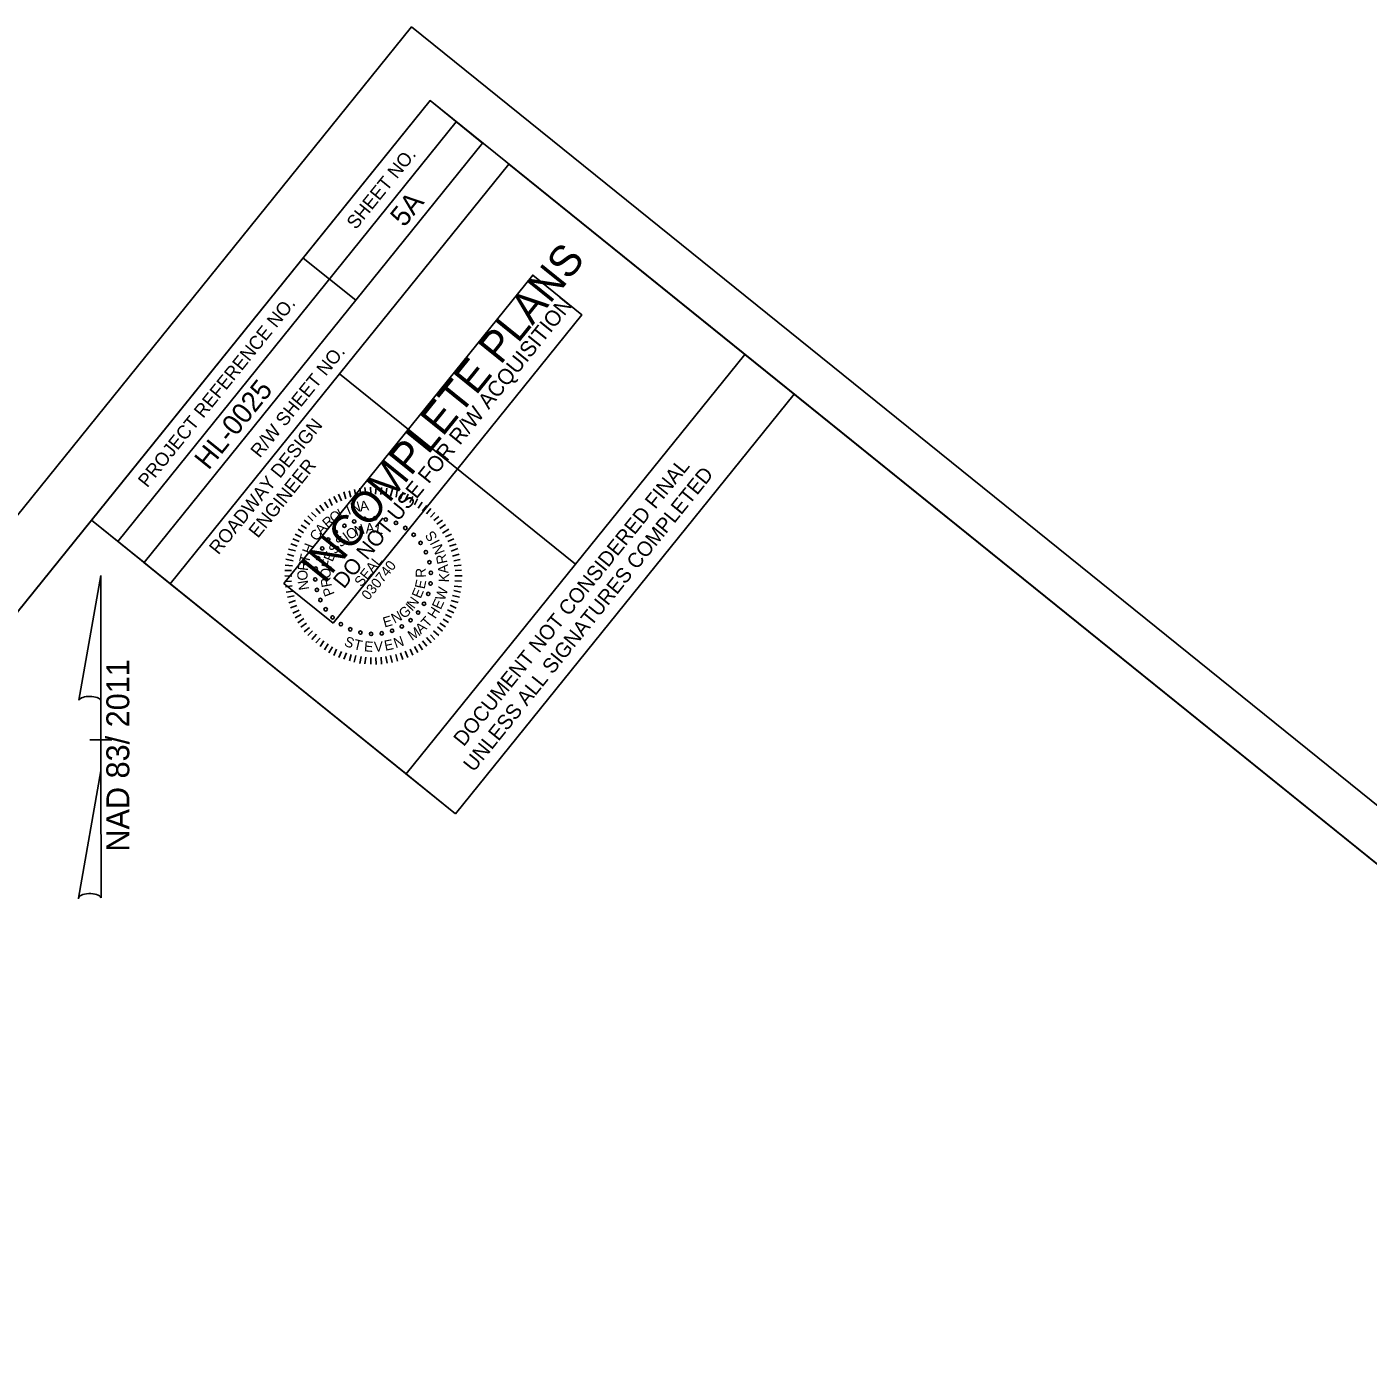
# Model space of a CAD drawing. Extents: x 1487825 to 1489784, y 498345 to 500343.
# Drawn here: x 1488789.3 to 1489286.9, y 499843.6 to 500343.2 of the extents above; entities that cross this region are included whole.
import ezdxf

# ---------------------------------------------------------------- set-up
doc = ezdxf.new("R2010")
doc.units = 0
for name, color, linetype in [('Old_Level_9', 7, 'Continuous'), ('Prop North Arrow NAD83 for Plan Sheets CELL', 7, 'Continuous'), ('Sheet Border Standard 30in CELL', 7, 'Continuous'), ('Sheet Clip Boundary CELL', 7, 'Continuous'), ('Sheet Data Field CELL', 7, 'Continuous'), ('Sheet Plan CELL', 7, 'Continuous'), ('Sheet Plot Border Outside CELL', 7, 'Continuous'), ('Sheet Sticker Exception Certification CELL', 7, 'Continuous'), ('Sheet Sticker Incomplete CELL', 7, 'Continuous')]:
    doc.layers.add(name, color=color, linetype=linetype)

msp = doc.modelspace()

# ---------------------------------------------------------------- linework, layer by layer
at = {"layer": 'Old_Level_9'}
for p, q in [((1488910.81, 500171.53), (1488911.36, 500169.03)), ((1488912.83, 500171.96), (1488913.22, 500169.58)), ((1488914.72, 500172.23), (1488915.07, 500169.64)), ((1488916.84, 500172.31), (1488916.89, 500169.83)), ((1488918.9, 500172.32), (1488918.67, 500169.81)), ((1488920.84, 500172.17), (1488920.61, 500169.66)), ((1488922.85, 500171.96), (1488922.48, 500169.43)), ((1488924.88, 500171.61), (1488924.23, 500169.05)), ((1488899.66, 500166.78), (1488901.08, 500164.72)), ((1488901.44, 500168.03), (1488902.56, 500165.59)), ((1488903.13, 500168.85), (1488904.36, 500166.71)), ((1488904.88, 500169.75), (1488906, 500167.31)), ((1488906.85, 500170.6), (1488907.63, 500168.06)), ((1488908.87, 500171.03), (1488909.49, 500168.61)), ((1488926.71, 500171.17), (1488926.26, 500168.7)), ((1488928.84, 500170.47), (1488927.83, 500167.95)), ((1488930.7, 500169.75), (1488929.67, 500167.36)), ((1488932.49, 500168.94), (1488931.31, 500166.68)), ((1488934.16, 500167.98), (1488933.04, 500165.8)), ((1488935.92, 500166.82), (1488934.52, 500164.61)), ((1488893.51, 500161.71), (1488895.35, 500159.84)), ((1488894.94, 500163), (1488896.68, 500161.34)), ((1488896.49, 500164.45), (1488898.05, 500162.55)), ((1488898, 500165.67), (1488899.42, 500163.62)), ((1488937.62, 500165.58), (1488936.05, 500163.63)), ((1488939.1, 500164.39), (1488937.53, 500162.44)), ((1488940.67, 500162.99), (1488939.01, 500161.25)), ((1488942.18, 500161.52), (1488940.28, 500159.96)), ((1488889.92, 500156.77), (1488891.91, 500155.42)), ((1488891.03, 500158.31), (1488893.09, 500157.04)), ((1488892.2, 500160.07), (1488894.22, 500158.44)), ((1488943.47, 500160.09), (1488941.35, 500158.58)), ((1488944.63, 500158.51), (1488942.52, 500157)), ((1488945.81, 500156.79), (1488943.48, 500155.33)), ((1488887.23, 500151.36), (1488889.53, 500150.4)), ((1488887.95, 500153.22), (1488890.34, 500152.19)), ((1488888.83, 500154.95), (1488891.02, 500153.83)), ((1488946.87, 500154.91), (1488944.55, 500153.95)), ((1488947.69, 500153.22), (1488945.45, 500152.2)), ((1488948.54, 500151.25), (1488946.07, 500150.41)), ((1488885.93, 500147.53), (1488888.29, 500146.78)), ((1488886.37, 500149.35), (1488889, 500148.78)), ((1488949.22, 500149.54), (1488946.69, 500148.63)), ((1488949.65, 500147.53), (1488947.24, 500146.77)), ((1488885.02, 500141.45), (1488887.51, 500141.37)), ((1488885.16, 500143.39), (1488887.82, 500143.18)), ((1488885.42, 500145.62), (1488888.04, 500145.05)), ((1488950.08, 500145.51), (1488947.64, 500145.04)), ((1488950.45, 500143.42), (1488947.84, 500143.21)), ((1488950.58, 500141.51), (1488948.17, 500141.39)), ((1488884.95, 500139.46), (1488887.59, 500139.38)), ((1488884.95, 500137.39), (1488887.44, 500137.45)), ((1488950.52, 500137.45), (1488948.02, 500137.54)), ((1488950.73, 500139.46), (1488948.03, 500139.46)), ((1488885.24, 500135.36), (1488887.7, 500135.7)), ((1488885.45, 500133.39), (1488887.97, 500133.81)), ((1488886.01, 500131.53), (1488888.45, 500132.01)), ((1488949.81, 500131.47), (1488947.25, 500132.12)), ((1488950.17, 500133.36), (1488947.69, 500133.95)), ((1488950.52, 500135.39), (1488947.87, 500135.6)), ((1488886.52, 500129.45), (1488888.91, 500130.35)), ((1488887.07, 500127.59), (1488889.46, 500128.49)), ((1488887.92, 500125.62), (1488890.36, 500126.74)), ((1488947.64, 500125.76), (1488945.4, 500126.8)), ((1488948.52, 500127.49), (1488946.28, 500128.53)), ((1488949.24, 500129.49), (1488946.66, 500130.28)), ((1488888.82, 500123.87), (1488891.11, 500125.11)), ((1488889.8, 500122.05), (1488892.05, 500123.58)), ((1488890.9, 500120.39), (1488893.01, 500121.9)), ((1488944.66, 500120.47), (1488942.51, 500121.94)), ((1488945.76, 500122.15), (1488943.7, 500123.42)), ((1488946.84, 500123.97), (1488944.58, 500125.15)), ((1488892.22, 500118.69), (1488894.18, 500120.32)), ((1488893.51, 500117.26), (1488895.31, 500119.02)), ((1488895.02, 500115.79), (1488896.73, 500117.75)), ((1488896.44, 500114.52), (1488898.16, 500116.34)), ((1488939.24, 500114.55), (1488937.61, 500116.51)), ((1488940.67, 500115.84), (1488938.99, 500117.58)), ((1488942.14, 500117.35), (1488940.18, 500119.06)), ((1488943.54, 500118.92), (1488941.59, 500120.49)), ((1488898.07, 500113.2), (1488899.48, 500115.27)), ((1488899.69, 500112.02), (1488901.09, 500114.23)), ((1488901.37, 500110.92), (1488902.63, 500113.12)), ((1488903.12, 500109.9), (1488904.22, 500112.22)), ((1488904.97, 500109.17), (1488906.01, 500111.42)), ((1488930.65, 500109.15), (1488929.61, 500111.53)), ((1488932.48, 500109.99), (1488931.46, 500112.22)), ((1488934.3, 500110.96), (1488933.05, 500113.25)), ((1488936.03, 500112), (1488934.67, 500114.13)), ((1488937.66, 500113.39), (1488936.11, 500115.28)), ((1488906.89, 500108.53), (1488907.85, 500110.83)), ((1488908.95, 500107.89), (1488909.55, 500110.23)), ((1488910.78, 500107.45), (1488911.3, 500109.85)), ((1488912.82, 500106.96), (1488913.33, 500109.5)), ((1488914.69, 500106.73), (1488915.06, 500109.26)), ((1488916.91, 500106.61), (1488916.92, 500109.17)), ((1488918.91, 500106.54), (1488918.7, 500109.15)), ((1488920.82, 500106.67), (1488920.69, 500109.22)), ((1488922.91, 500107.04), (1488922.44, 500109.48)), ((1488924.8, 500107.31), (1488924.17, 500109.88)), ((1488926.82, 500107.74), (1488926.12, 500110.23)), ((1488928.8, 500108.45), (1488927.91, 500110.85))]:
    msp.add_line(p, q, dxfattribs=at)
for centre in [(1488918.52, 500160.83), (1488903.85, 500155.74), (1488907.1, 500158.02), (1488910.71, 500159.65), (1488914.56, 500160.6), (1488922.45, 500160.32), (1488926.23, 500159.1), (1488929.71, 500157.21), (1488901.08, 500152.91), (1488932.79, 500154.7), (1488935.35, 500151.68), (1488897.31, 500145.97), (1488898.87, 500149.61), (1488937.32, 500148.24), (1488896.44, 500142.1), (1488938.62, 500144.49), (1488896.3, 500138.13), (1488939.06, 500136.61), (1488939.2, 500140.57), (1488896.89, 500134.21), (1488938.19, 500132.74), (1488898.18, 500130.47), (1488900.15, 500127.02), (1488934.42, 500125.8), (1488936.63, 500129.09), (1488902.72, 500124), (1488905.79, 500121.5), (1488928.4, 500120.69), (1488931.65, 500122.96), (1488909.28, 500119.6), (1488913.05, 500118.38), (1488916.98, 500117.88), (1488920.94, 500118.1), (1488924.79, 500119.05)]:
    msp.add_circle(centre, 0.63, dxfattribs=at)
at = {"layer": 'Prop North Arrow NAD83 for Plan Sheets CELL'}
for p, q in [((1488808.52, 500093.27), (1488816.72, 500139.62)), ((1488816.77, 500139.62), (1488816.72, 500139.62)), ((1488816.77, 500139.62), (1488816.72, 500139.62)), ((1488816.77, 500139.62), (1488816.77, 500091.82)), ((1488816.77, 500067.02), (1488816.77, 500093.22)), ((1488816.77, 500091.82), (1488816.77, 500093.17)), ((1488812.77, 500078.62), (1488812.72, 500078.62)), ((1488816.32, 500078.62), (1488812.77, 500078.62)), ((1488812.82, 500078.62), (1488820.82, 500078.62)), ((1488816.77, 500067.02), (1488808.42, 500019.77)), ((1488816.82, 500019.97), (1488816.77, 500067.02))]:
    msp.add_line(p, q, dxfattribs=at)
for centre, start_param, end_param in [((1488812.65, 500092.77), 0.216388, 2.908219), ((1488812.65, 500019.6), 0.201328, 3.141593)]:
    msp.add_ellipse(centre, major_axis=(4.23, -0.03), ratio=0.461098, start_param=start_param, end_param=end_param, dxfattribs=at)
at = {"layer": 'Sheet Border Standard 30in CELL'}
msp.add_line((1488832.75, 500144.36), (1488842.48, 500136.51), dxfattribs=at)
at = {"layer": 'Sheet Clip Boundary CELL'}
msp.add_lwpolyline([(1488948.36, 500051.16), (1488813.25, 500160.1), (1488087.84, 499260.53), (1488879.09, 498569.08), (1489756.18, 499656.68), (1489073.94, 500206.87)], close=True, dxfattribs=at)
at = {"layer": 'Sheet Plan CELL'}
for p, q in [((1488823.01, 500152.21), (1488948.61, 500307.93)), ((1488832.78, 500144.35), (1488958.34, 500300.08)), ((1488832.78, 500144.35), (1488958.34, 500300.08)), ((1488891.79, 500257.37), (1488911.28, 500241.71)), ((1488905.31, 500214.39), (1488992.86, 500143.81)), ((1488832.78, 500144.35), (1488842.5, 500136.51))]:
    msp.add_line(p, q, dxfattribs=at)
for points in [[(1488938.86, 500315.83), (1487997.21, 499148.18), (1488814.55, 498489.05), (1489756.18, 499656.68)], [(1488813.25, 500160.1), (1488938.86, 500315.83), (1488958.34, 500300.08), (1488832.78, 500144.35)], [(1488905.31, 500214.39), (1488968.07, 500292.23), (1489055.66, 500221.61), (1488992.89, 500143.76)], [(1488814.55, 498489.05), (1487997.21, 499148.15), (1488813.25, 500160.1), (1488930.07, 500065.91), (1489055.66, 500221.61), (1489756.18, 499656.68)], [(1488842.5, 500136.51), (1488905.31, 500214.39), (1488992.89, 500143.76), (1488930.07, 500065.91)]]:
    msp.add_lwpolyline(points, close=True, dxfattribs=at)
at = {"layer": 'Sheet Plot Border Outside CELL'}
msp.add_lwpolyline([(1488727.56, 498345.32), (1489784.38, 499655.78), (1488932.01, 500343.17), (1487875.19, 499032.7)], close=True, dxfattribs=at)
at = {"layer": 'Sheet Sticker Exception Certification CELL'}
for p, q in [((1488930.07, 500065.91), (1489055.65, 500221.62)), ((1488930.07, 500065.91), (1489055.65, 500221.62)), ((1489055.66, 500221.61), (1489073.95, 500206.86)), ((1489055.66, 500221.61), (1489073.95, 500206.86)), ((1489073.94, 500206.87), (1488948.36, 500051.16)), ((1489073.94, 500206.87), (1488948.36, 500051.16)), ((1488948.36, 500051.16), (1488930.07, 500065.91)), ((1488948.36, 500051.16), (1488930.07, 500065.91))]:
    msp.add_line(p, q, dxfattribs=at)
at = {"layer": 'Sheet Sticker Incomplete CELL'}
msp.add_lwpolyline([(1488902.95, 500121.87), (1488884.66, 500136.62), (1488976.94, 500251.05), (1488995.23, 500236.3)], close=True, dxfattribs=at)

# ---------------------------------------------------------------- texts
at = {"layer": 'Old_Level_9'}
for s, height, rotation, p in [('N', 3.78, 16.0195, (1488909.99, 500162.55)), ('A', 3.78, 8.1207, (1488913.04, 500163.3)), ('R', 3.78, 41.1372, (1488900.93, 500156.88)), ('O', 3.78, 34.2024, (1488903.14, 500158.83)), ('L', 3.78, 26.8616, (1488905.72, 500160.6)), ('I', 3.78, 21.9216, (1488908.63, 500161.98)), ('C', 3.78, 56.0556, (1488897.04, 500152.06)), ('A', 3.78, 49.0905, (1488898.7, 500154.44)), ('O', 3.76, 28.9905, (1488908.99, 500152.7)), ('N', 3.76, 18.5087, (1488911.54, 500154.11)), ('A', 3.76, 5.0594, (1488915.06, 500155.13)), ('L', 3.76, 352.648, (1488918.66, 500155.3)), ('H', 3.78, 68.859, (1488894.78, 500147.19)), ('S', 3.76, 55.5837, (1488903.95, 500147.25)), ('S', 3.76, 44.1571, (1488905.88, 500149.81)), ('I', 3.76, 36.5977, (1488908.2, 500152.05)), ('S', 3.78, 123.3735, (1488941.78, 500153.72)), ('I', 3.78, 117.162, (1488942.66, 500152.11)), ('N', 3.78, 110.4882, (1488944.41, 500148.22)), ('T', 3.78, 76.5514, (1488893.93, 500143.9)), ('E', 3.76, 67.7046, (1488902.69, 500144.41)), ('R', 3.78, 102.266, (1488945.38, 500144.27)), ('O', 3.78, 91.0599, (1488893.45, 500137.74)), ('R', 3.78, 83.2911, (1488893.51, 500141.16)), ('O', 3.76, 89.3675, (1488901.98, 500138.44)), ('F', 3.76, 77.5156, (1488902.17, 500142.01)), ('SEAL', 3.759, 51.1156, (1488913.38, 500135.1)), ('030740', 3.759, 51.1156, (1488916.01, 500130.15)), ('R', 3.76, 91.4649, (1488937.36, 500138.81)), ('A', 3.78, 94.6373, (1488945.73, 500140.45)), ('N', 3.78, 99.1823, (1488894.02, 500134.45)), ('R', 3.76, 100.8634, (1488902.5, 500135.58)), ('E', 3.76, 78.2725, (1488936.84, 500134.35)), ('K', 3.78, 87.2567, (1488945.84, 500136.98)), ('P', 3.76, 111.2393, (1488903.52, 500132.7)), ('N', 3.76, 54.2434, (1488932.94, 500126.96)), ('E', 3.76, 66.9213, (1488935.37, 500130.78)), ('W', 3.78, 73.1214, (1488944.26, 500129.97)), ('N', 3.76, 27.174, (1488925.68, 500121.63)), ('G', 3.76, 38.5969, (1488929.13, 500123.35)), ('I', 3.76, 46.7402, (1488932.18, 500126.03)), ('H', 3.78, 57.1269, (1488940.81, 500123.25)), ('E', 3.78, 65.2804, (1488942.83, 500126.68)), ('E', 3.76, 15.9848, (1488921.99, 500120.24)), ('A', 3.78, 41.2978, (1488935.42, 500117.63)), ('T', 3.78, 48.5022, (1488937.99, 500119.93)), ('S', 3.78, 339.3277, (1488906.72, 500113.61)), ('N', 3.78, 19.4446, (1488926.13, 500112.53)), ('M', 3.78, 33.4527, (1488932.17, 500115.24)), ('T', 3.78, 346.74, (1488910.21, 500112.32)), ('E', 3.78, 354.9381, (1488914.25, 500111.47)), ('V', 3.78, 3.0454, (1488918.14, 500111.23)), ('E', 3.78, 11.3469, (1488922.27, 500111.62))]:
    msp.add_text(s, height=height, rotation=rotation, dxfattribs=at).set_placement(p)
at = {"layer": 'Prop North Arrow NAD83 for Plan Sheets CELL'}
msp.add_text('NAD 83/ 2011', height=8.5, rotation=90, dxfattribs=at).set_placement((1488827.29, 500037.1))
at = {"layer": 'Sheet Data Field CELL'}
for s, p in [('5A', (1488929.29, 500268.52)), ('HL-0025', (1488856.69, 500178.4))]:
    msp.add_text(s, height=7.5, rotation=51.1157, dxfattribs=at).set_placement(p)
at = {"layer": 'Sheet Plan CELL'}
for s, height, p in [('SHEET NO.', 5, (1488911.38, 500267.71)), ('PROJECT REFERENCE NO.', 5.0001, (1488833.98, 500171.91)), ('R/W SHEET NO.', 5.0001, (1488875.72, 500182.95)), ('ROADWAY DESIGN', 5.0001, (1488860.35, 500147.01)), ('ENGINEER', 5, (1488875, 500153.17))]:
    msp.add_text(s, height=height, rotation=51.1157, dxfattribs=at).set_placement(p)
at = {"layer": 'Sheet Sticker Exception Certification CELL'}
for s, p in [('DOCUMENT NOT CONSIDERED FINAL', (1488951.35, 500075.82)), ('DOCUMENT NOT CONSIDERED FINAL', (1488951.35, 500075.82)), ('UNLESS ALL SIGNATURES COMPLETED', (1488955.02, 500066.35)), ('UNLESS ALL SIGNATURES COMPLETED', (1488955.02, 500066.35))]:
    msp.add_text(s, height=5.5, rotation=51.1156, dxfattribs=at).set_placement(p)
at = {"layer": 'Sheet Sticker Incomplete CELL'}
for s, height, p in [('INCOMPLETE PLANS', 11.52, (1488899.47, 500136.18)), ('DO NOT USE FOR R/W ACQUISITION', 5.76, (1488906.92, 500134.35))]:
    msp.add_text(s, height=height, rotation=51.1156, dxfattribs=at).set_placement(p)

doc.saveas('drawing.dxf')
